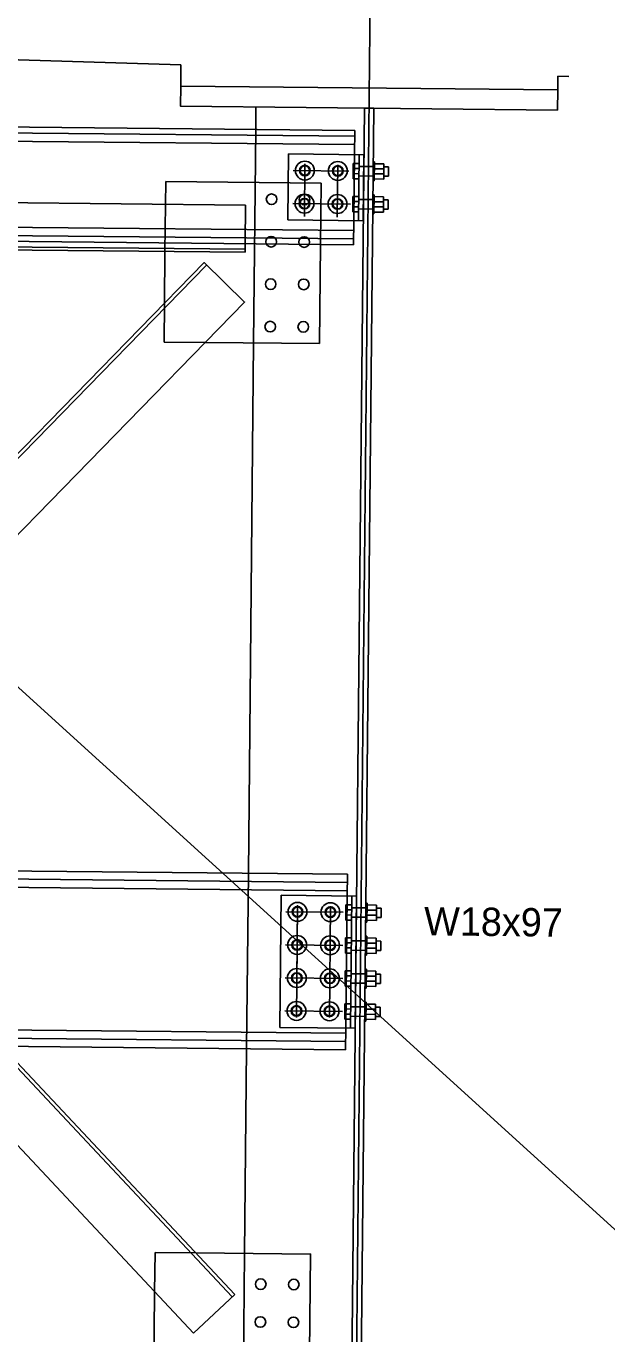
# Model space of a CAD drawing. Extents: x 632312 to 632885, y 378199 to 378534.
# Drawn here: x 632730.99 to 632736.12, y 378449.38 to 378460.93 of the extents above; entities that cross this region are included whole.
import ezdxf

# ---------------------------------------------------------------- set-up
doc = ezdxf.new("R2010")
doc.units = 0
for name, color, linetype in [('B_Boring', 7, 'Continuous'), ('B_Boring Annot', 7, 'Continuous'), ('R_Proposed Const Limits Cut', 7, 'Continuous'), ('R_Shade Removal', 7, 'Continuous'), ('R_Wall', 7, 'Continuous'), ('SHT_Dimensions', 7, 'Continuous'), ('USACE_Easement', 7, 'Continuous')]:
    doc.layers.add(name, color=color, linetype=linetype)

msp = doc.modelspace()

# ---------------------------------------------------------------- linework, layer by layer
at = {"layer": 'B_Boring'}
for p, q in [((632733.015, 378460.013), (632733.017, 378460.212)), ((632733.89, 378460.005), (632722.89, 378460.114)), ((632733.889, 378459.954), (632722.89, 378460.064)), ((632733.888, 378459.792), (632733.89, 378460.005)), ((632733.304, 378459.798), (632733.299, 378459.215)), ((632733.971, 378459.791), (632733.304, 378459.798)), ((632733.924, 378459.208), (632733.929, 378459.792)), ((632733.965, 378459.208), (632733.971, 378459.791)), ((632733.877, 378459.714), (632733.875, 378459.579)), ((632733.929, 378459.714), (632733.877, 378459.714)), ((632733.929, 378459.714), (632733.927, 378459.578)), ((632734.054, 378459.728), (632734.052, 378459.561)), ((632734.054, 378459.728), (632734.064, 378459.728)), ((632734.064, 378459.728), (632734.063, 378459.561)), ((632734.064, 378459.712), (632734.147, 378459.711)), ((632734.147, 378459.711), (632734.146, 378459.576)), ((632734.147, 378459.685), (632734.189, 378459.685)), ((632734.189, 378459.685), (632734.188, 378459.602)), ((632733.927, 378459.578), (632733.875, 378459.579)), ((632733.928, 378459.668), (632733.876, 378459.669)), ((632733.928, 378459.623), (632733.876, 378459.624)), ((632734.052, 378459.561), (632734.063, 378459.561)), ((632734.063, 378459.622), (632734.146, 378459.621)), ((632734.063, 378459.577), (632734.146, 378459.576)), ((632734.064, 378459.667), (632734.147, 378459.666)), ((632734.146, 378459.602), (632734.188, 378459.602)), ((632732.219, 378459.554), (632732.219, 378459.554)), ((632733.874, 378459.422), (632733.872, 378459.287)), ((632733.925, 378459.377), (632733.873, 378459.377)), ((632733.925, 378459.332), (632733.873, 378459.332)), ((632733.926, 378459.422), (632733.874, 378459.422)), ((632733.926, 378459.422), (632733.924, 378459.287)), ((632734.051, 378459.436), (632734.049, 378459.27)), ((632734.051, 378459.436), (632734.061, 378459.436)), ((632734.061, 378459.436), (632734.06, 378459.27)), ((632734.06, 378459.33), (632734.144, 378459.33)), ((632734.061, 378459.421), (632734.144, 378459.42)), ((632734.061, 378459.375), (632734.144, 378459.375)), ((632734.144, 378459.42), (632734.143, 378459.284)), ((632734.144, 378459.394), (632734.186, 378459.393)), ((632734.186, 378459.393), (632734.185, 378459.31)), ((632733.299, 378459.215), (632733.965, 378459.208)), ((632733.924, 378459.287), (632733.872, 378459.287)), ((632734.049, 378459.27), (632734.06, 378459.27)), ((632734.06, 378459.285), (632734.143, 378459.284)), ((632734.143, 378459.31), (632734.185, 378459.31)), ((632733.88, 378458.996), (632722.88, 378459.106)), ((632733.88, 378459.047), (632722.881, 378459.156)), ((632733.882, 378459.209), (632733.88, 378458.996)), ((632732.921, 378458.93), (632732.922, 378459.006)), ((632733.579, 378458.123), (632733.588, 378458.999)), ((632728.379, 378458.975), (632732.921, 378458.93)), ((632732.569, 378458.133), (632733.579, 378458.123)), ((632732.95, 378453.445), (632732.996, 378458.129)), ((632733.824, 378453.364), (632722.824, 378453.474)), ((632733.825, 378453.437), (632722.825, 378453.546)), ((632733.823, 378453.245), (632733.825, 378453.437)), ((632733.239, 378453.251), (632733.228, 378452.084)), ((632733.906, 378453.244), (632733.239, 378453.251)), ((632733.853, 378452.078), (632733.864, 378453.245)), ((632733.906, 378453.244), (632733.894, 378452.078)), ((632733.811, 378453.167), (632733.81, 378453.032)), ((632733.864, 378453.167), (632733.811, 378453.167)), ((632733.863, 378453.121), (632733.811, 378453.122)), ((632733.905, 378453.14), (632733.988, 378453.139)), ((632733.987, 378453.014), (632733.989, 378453.181)), ((632733.989, 378453.181), (632733.999, 378453.181)), ((632733.999, 378453.181), (632733.997, 378453.014)), ((632733.998, 378453.12), (632734.082, 378453.119)), ((632733.999, 378453.165), (632734.082, 378453.164)), ((632734.082, 378453.164), (632734.081, 378453.029)), ((632734.082, 378453.138), (632734.124, 378453.138)), ((632734.124, 378453.138), (632734.123, 378453.055)), ((632733.862, 378453.031), (632733.81, 378453.032)), ((632733.863, 378453.076), (632733.811, 378453.077)), ((632733.904, 378453.057), (632733.987, 378453.056)), ((632733.987, 378453.014), (632733.997, 378453.014)), ((632733.998, 378453.075), (632734.081, 378453.074)), ((632733.998, 378453.03), (632734.081, 378453.029)), ((632734.081, 378453.055), (632734.123, 378453.055)), ((632733.809, 378452.875), (632733.807, 378452.74)), ((632733.861, 378452.875), (632733.809, 378452.875)), ((632733.984, 378452.723), (632733.986, 378452.889)), ((632733.986, 378452.889), (632733.996, 378452.889)), ((632733.996, 378452.889), (632733.995, 378452.723)), ((632733.996, 378452.874), (632734.079, 378452.873)), ((632734.079, 378452.873), (632734.078, 378452.737)), ((632733.86, 378452.83), (632733.808, 378452.83)), ((632733.86, 378452.785), (632733.808, 378452.785)), ((632733.995, 378452.783), (632734.078, 378452.782)), ((632733.996, 378452.828), (632734.079, 378452.828)), ((632734.078, 378452.763), (632734.12, 378452.763)), ((632734.079, 378452.847), (632734.121, 378452.846)), ((632734.121, 378452.846), (632734.12, 378452.763)), ((632733.859, 378452.74), (632733.807, 378452.74)), ((632733.984, 378452.723), (632733.995, 378452.723)), ((632733.995, 378452.738), (632734.078, 378452.737)), ((632733.806, 378452.584), (632733.804, 378452.448)), ((632733.857, 378452.538), (632733.805, 378452.539)), ((632733.858, 378452.583), (632733.806, 378452.584)), ((632733.981, 378452.431), (632733.983, 378452.598)), ((632733.983, 378452.598), (632733.993, 378452.598)), ((632733.993, 378452.598), (632733.992, 378452.431)), ((632733.993, 378452.582), (632734.076, 378452.581)), ((632733.993, 378452.537), (632734.076, 378452.536)), ((632734.076, 378452.581), (632734.075, 378452.446)), ((632734.076, 378452.555), (632734.118, 378452.555)), ((632734.118, 378452.555), (632734.117, 378452.471)), ((632733.856, 378452.448), (632733.804, 378452.448)), ((632733.857, 378452.493), (632733.805, 378452.494)), ((632733.981, 378452.431), (632733.992, 378452.431)), ((632733.992, 378452.492), (632734.076, 378452.491)), ((632733.992, 378452.447), (632734.075, 378452.446)), ((632734.075, 378452.472), (632734.117, 378452.471)), ((632733.803, 378452.292), (632733.801, 378452.157)), ((632733.855, 378452.292), (632733.803, 378452.292)), ((632733.978, 378452.139), (632733.98, 378452.306)), ((632733.98, 378452.306), (632733.99, 378452.306)), ((632733.99, 378452.306), (632733.989, 378452.139)), ((632733.99, 378452.29), (632734.074, 378452.289)), ((632734.074, 378452.289), (632734.072, 378452.154)), ((632733.854, 378452.246), (632733.802, 378452.247)), ((632733.854, 378452.201), (632733.802, 378452.202)), ((632733.989, 378452.2), (632734.073, 378452.199)), ((632733.99, 378452.245), (632734.073, 378452.244)), ((632734.072, 378452.18), (632734.114, 378452.18)), ((632734.073, 378452.263), (632734.115, 378452.263)), ((632734.115, 378452.263), (632734.114, 378452.18)), ((632733.81, 378451.959), (632722.81, 378452.069)), ((632733.228, 378452.084), (632733.894, 378452.078)), ((632733.853, 378452.156), (632733.801, 378452.157)), ((632733.809, 378451.887), (632733.811, 378452.079)), ((632733.978, 378452.139), (632733.989, 378452.139)), ((632733.989, 378452.155), (632734.072, 378452.154)), ((632733.809, 378451.887), (632722.81, 378451.996)), ((632732.916, 378450.088), (632732.934, 378451.896)), ((632732.829, 378449.725), (632732.465, 378449.383))]:
    msp.add_line(p, q, dxfattribs=at)
for points in [[(632735.683, 378460.186), (632735.685, 378460.363), (632732.352, 378460.396), (632732.35, 378460.219)], [(632733.939, 378448.203), (632733.856, 378448.203), (632733.975, 378460.203), (632734.058, 378460.202)]]:
    msp.add_lwpolyline(points, close=True, dxfattribs=at)
for points in [[(632732.212, 378458.937), (632732.208, 378458.479)], [(632729.139, 378454.621), (632732.916, 378458.489), (632732.559, 378458.838), (632729.144, 378455.342)], [(632732.465, 378449.383), (632730.08, 378451.924)], [(632730.772, 378451.917), (632732.829, 378449.725)], [(632732.121, 378449.749), (632732.107, 378448.346), (632732.107, 378448.346), (632732.107, 378448.346), (632733.482, 378448.332), (632733.499, 378450.082), (632732.485, 378450.092)]]:
    msp.add_lwpolyline(points, dxfattribs=at)
for centre in [(632733.449, 378459.651), (632733.74, 378459.648), (632733.155, 378459.398), (632733.446, 378459.395), (632733.446, 378459.359), (632733.738, 378459.356), (632733.151, 378459.023), (632733.443, 378459.02), (632733.147, 378458.648), (632733.439, 378458.646), (632733.143, 378458.273), (632733.435, 378458.271), (632733.384, 378453.104), (632733.675, 378453.101), (632733.381, 378452.812), (632733.672, 378452.809), (632733.378, 378452.52), (632733.67, 378452.517), (632733.375, 378452.229), (632733.667, 378452.226), (632733.059, 378449.816), (632733.351, 378449.813), (632733.056, 378449.482), (632733.348, 378449.479)]:
    msp.add_circle(centre, 0.0469, dxfattribs=at)
at = {"layer": 'B_Boring Annot'}
for p, q in [((632728.397, 378460.704), (632732.354, 378460.586)), ((632732.354, 378460.586), (632732.352, 378460.396)), ((632735.685, 378460.363), (632735.686, 378460.486)), ((632735.686, 378460.486), (632735.783, 378460.483)), ((632732.352, 378460.396), (632735.685, 378460.363))]:
    msp.add_line(p, q, dxfattribs=at)
at = {"layer": 'R_Proposed Const Limits Cut'}
for p, q in [((632733.889, 378459.88), (632722.889, 378459.989)), ((632732.996, 378458.129), (632733.015, 378460.013)), ((632733.882, 378459.209), (632733.888, 378459.792)), ((632733.928, 378459.688), (632734.053, 378459.686)), ((632733.928, 378459.604), (632734.053, 378459.603)), ((632732.212, 378458.937), (632732.219, 378459.554)), ((632733.594, 378459.54), (632732.219, 378459.554)), ((632733.594, 378459.54), (632733.588, 378458.999)), ((632732.925, 378459.346), (632723.842, 378459.437)), ((632732.922, 378459.006), (632732.925, 378459.346)), ((632733.925, 378459.396), (632734.05, 378459.395)), ((632733.881, 378459.121), (632722.882, 378459.231)), ((632733.925, 378459.313), (632734.05, 378459.311)), ((632732.921, 378458.956), (632723.838, 378459.046)), ((632724.175, 378458.9), (632732.806, 378449.704)), ((632732.581, 378458.816), (632723.769, 378449.794)), ((632732.208, 378458.479), (632732.205, 378458.137)), ((632732.569, 378458.133), (632732.205, 378458.137)), ((632732.95, 378453.445), (632732.934, 378451.896)), ((632733.823, 378453.291), (632722.824, 378453.4)), ((632733.823, 378453.245), (632733.811, 378452.079)), ((632733.863, 378453.141), (632733.905, 378453.14)), ((632733.862, 378453.057), (632733.904, 378453.057)), ((632733.86, 378452.849), (632733.985, 378452.848)), ((632733.86, 378452.766), (632733.985, 378452.764)), ((632733.857, 378452.557), (632733.982, 378452.556)), ((632733.857, 378452.474), (632733.982, 378452.473)), ((632733.854, 378452.182), (632733.979, 378452.181)), ((632733.855, 378452.266), (632733.98, 378452.264)), ((632733.811, 378452.033), (632722.811, 378452.142)), ((632732.121, 378449.749), (632732.125, 378450.096)), ((632732.485, 378450.092), (632732.125, 378450.096)), ((632732.916, 378450.088), (632732.899, 378448.338))]:
    msp.add_line(p, q, dxfattribs=at)
for centre, radius in [((632733.449, 378459.651), 0.0833), ((632733.449, 378459.651), 0.0417), ((632733.74, 378459.648), 0.0833), ((632733.74, 378459.648), 0.0417), ((632733.446, 378459.359), 0.0833), ((632733.446, 378459.359), 0.0417), ((632733.738, 378459.356), 0.0833), ((632733.738, 378459.356), 0.0417), ((632733.384, 378453.104), 0.0833), ((632733.384, 378453.104), 0.0417), ((632733.675, 378453.101), 0.0833), ((632733.675, 378453.101), 0.0417), ((632733.381, 378452.812), 0.0833), ((632733.672, 378452.809), 0.0833), ((632733.381, 378452.812), 0.0417), ((632733.672, 378452.809), 0.0417), ((632733.378, 378452.52), 0.0833), ((632733.378, 378452.52), 0.0417), ((632733.67, 378452.517), 0.0833), ((632733.67, 378452.517), 0.0417), ((632733.375, 378452.229), 0.0833), ((632733.667, 378452.226), 0.0833), ((632733.375, 378452.229), 0.0417), ((632733.667, 378452.226), 0.0417)]:
    msp.add_circle(centre, radius, dxfattribs=at)
at = {"layer": 'R_Shade Removal'}
msp.add_line((632733.886, 378447.026), (632734.036, 378462.091), dxfattribs=at)
at = {"layer": 'R_Wall'}
for p, q in [((632733.449, 378459.711), (632733.445, 378459.246)), ((632733.741, 378459.702), (632733.736, 378459.239)), ((632733.345, 378459.652), (632733.839, 378459.647)), ((632733.342, 378459.36), (632733.852, 378459.355)), ((632733.28, 378453.105), (632733.789, 378453.1)), ((632733.384, 378453.164), (632733.374, 378452.171)), ((632733.676, 378453.155), (632733.666, 378452.17)), ((632733.277, 378452.813), (632733.786, 378452.808)), ((632733.274, 378452.521), (632733.784, 378452.516)), ((632733.271, 378452.23), (632733.781, 378452.225))]:
    msp.add_line(p, q, dxfattribs=at)
at = {"layer": 'SHT_Dimensions'}
for p, q in [((632733.384, 378453.164), (632733.377, 378452.474)), ((632733.864, 378453.167), (632733.862, 378453.031)), ((632733.861, 378452.875), (632733.859, 378452.74)), ((632733.858, 378452.583), (632733.856, 378452.448)), ((632733.855, 378452.292), (632733.853, 378452.156))]:
    msp.add_line(p, q, dxfattribs=at)
at = {"layer": 'USACE_Easement'}
msp.add_line((632719.183, 378465.738), (632748.89, 378438.765), dxfattribs=at)

# ---------------------------------------------------------------- texts
at = {"layer": 'SHT_Dimensions'}
msp.add_text('W18x97', height=0.25, rotation=359.4304, dxfattribs=at).set_placement((632734.502, 378452.897))

doc.saveas('drawing.dxf')
